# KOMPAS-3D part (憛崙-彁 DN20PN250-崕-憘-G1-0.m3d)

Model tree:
1. Объединить компоненты:1  (labels: СЕНС-ПР DN20PN250-НО-G1-0)
2. Эскиз:1
3. Операция выдавливания:1
     Расстояние 1 = 14
4. Фаска:1
     Угол = 45; Длина 1 = 2; Длина 2 = 2

Referenced files in D:\Савин\!СЕНСОР\3D для заказчика\!Новый перечень\СЕНС-ПР\6. СЕНС-ПР-PN250-НО\DN20\: СЕНС-ПР DN20PN250-НО-G1-0.a3d
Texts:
  СЕНС-ПР DN20PN250-НО-СВ-G1-0
  ООО НПП Сенсор
  СЕНС-ПР DN20PN250-НО-G1-0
